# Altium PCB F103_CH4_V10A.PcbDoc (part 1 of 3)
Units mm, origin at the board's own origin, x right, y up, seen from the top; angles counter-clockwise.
Board outline 100.1 x 70.1 mm, 2 copper layers (TOP, BOTTOM), stack 1.6 mm thick; 116 components, 94 nets, 464 pads, 459 vias.
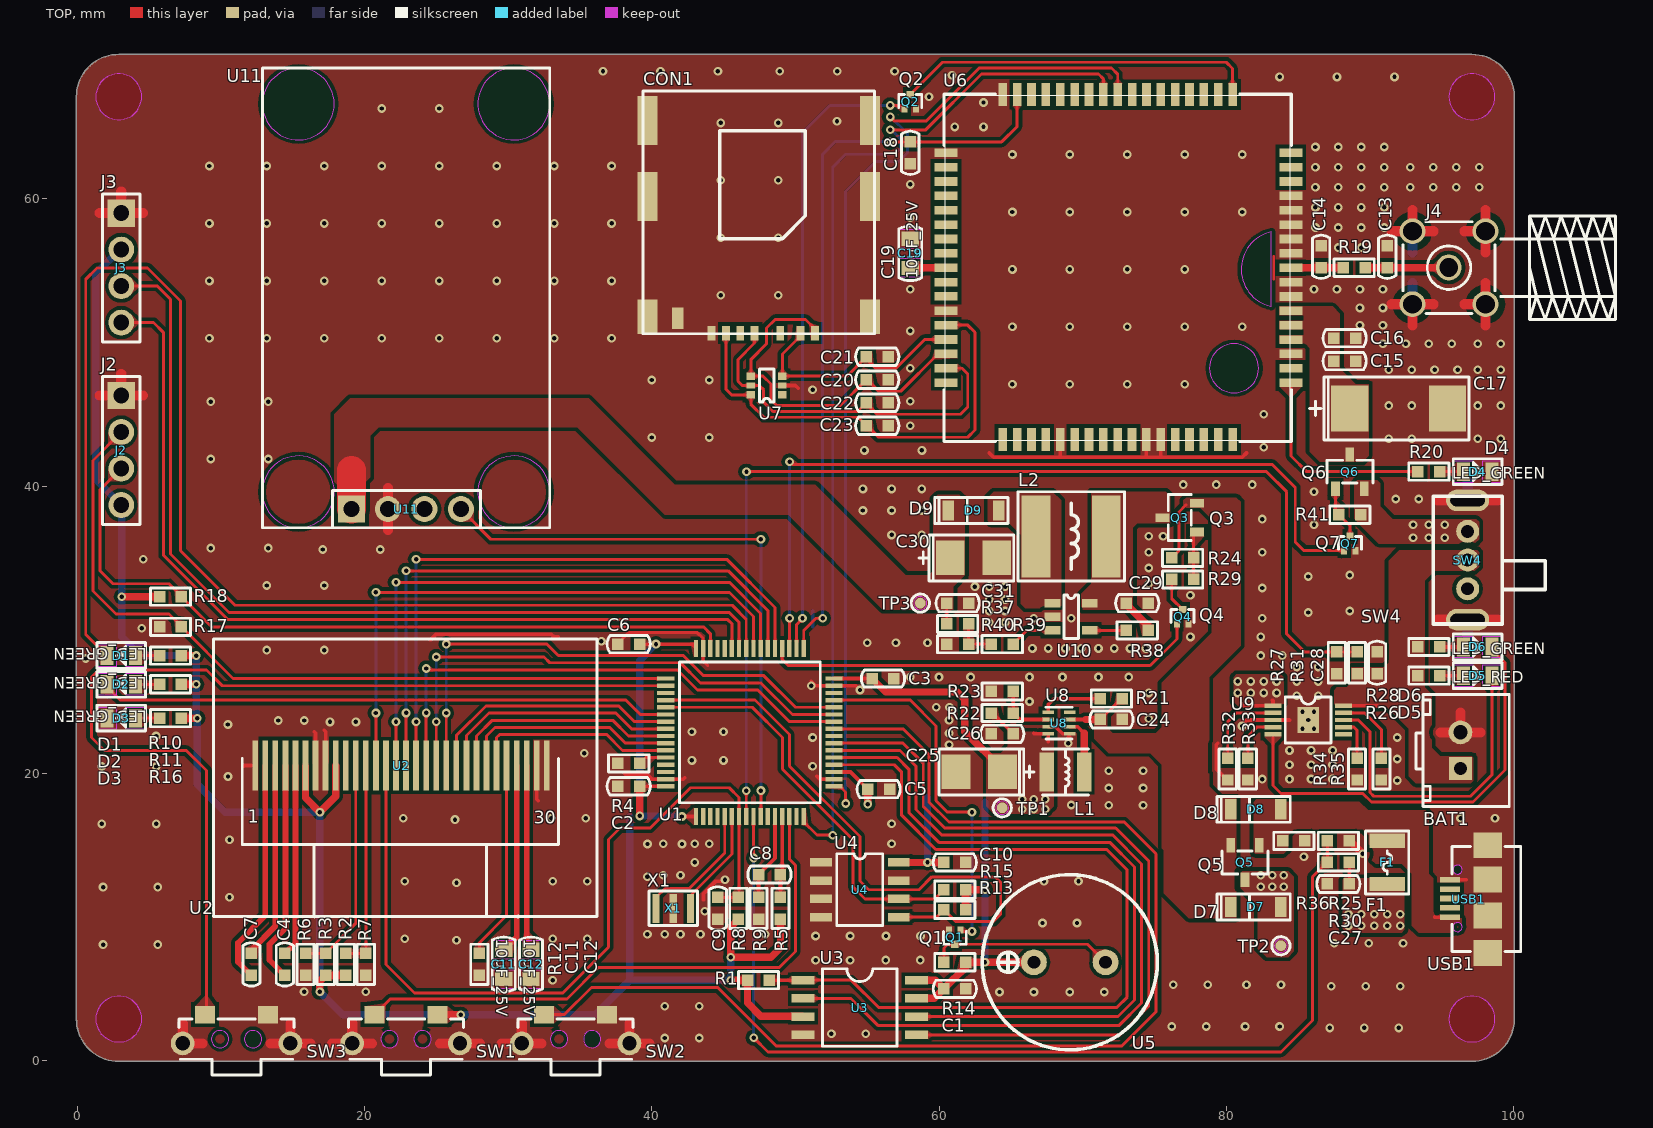
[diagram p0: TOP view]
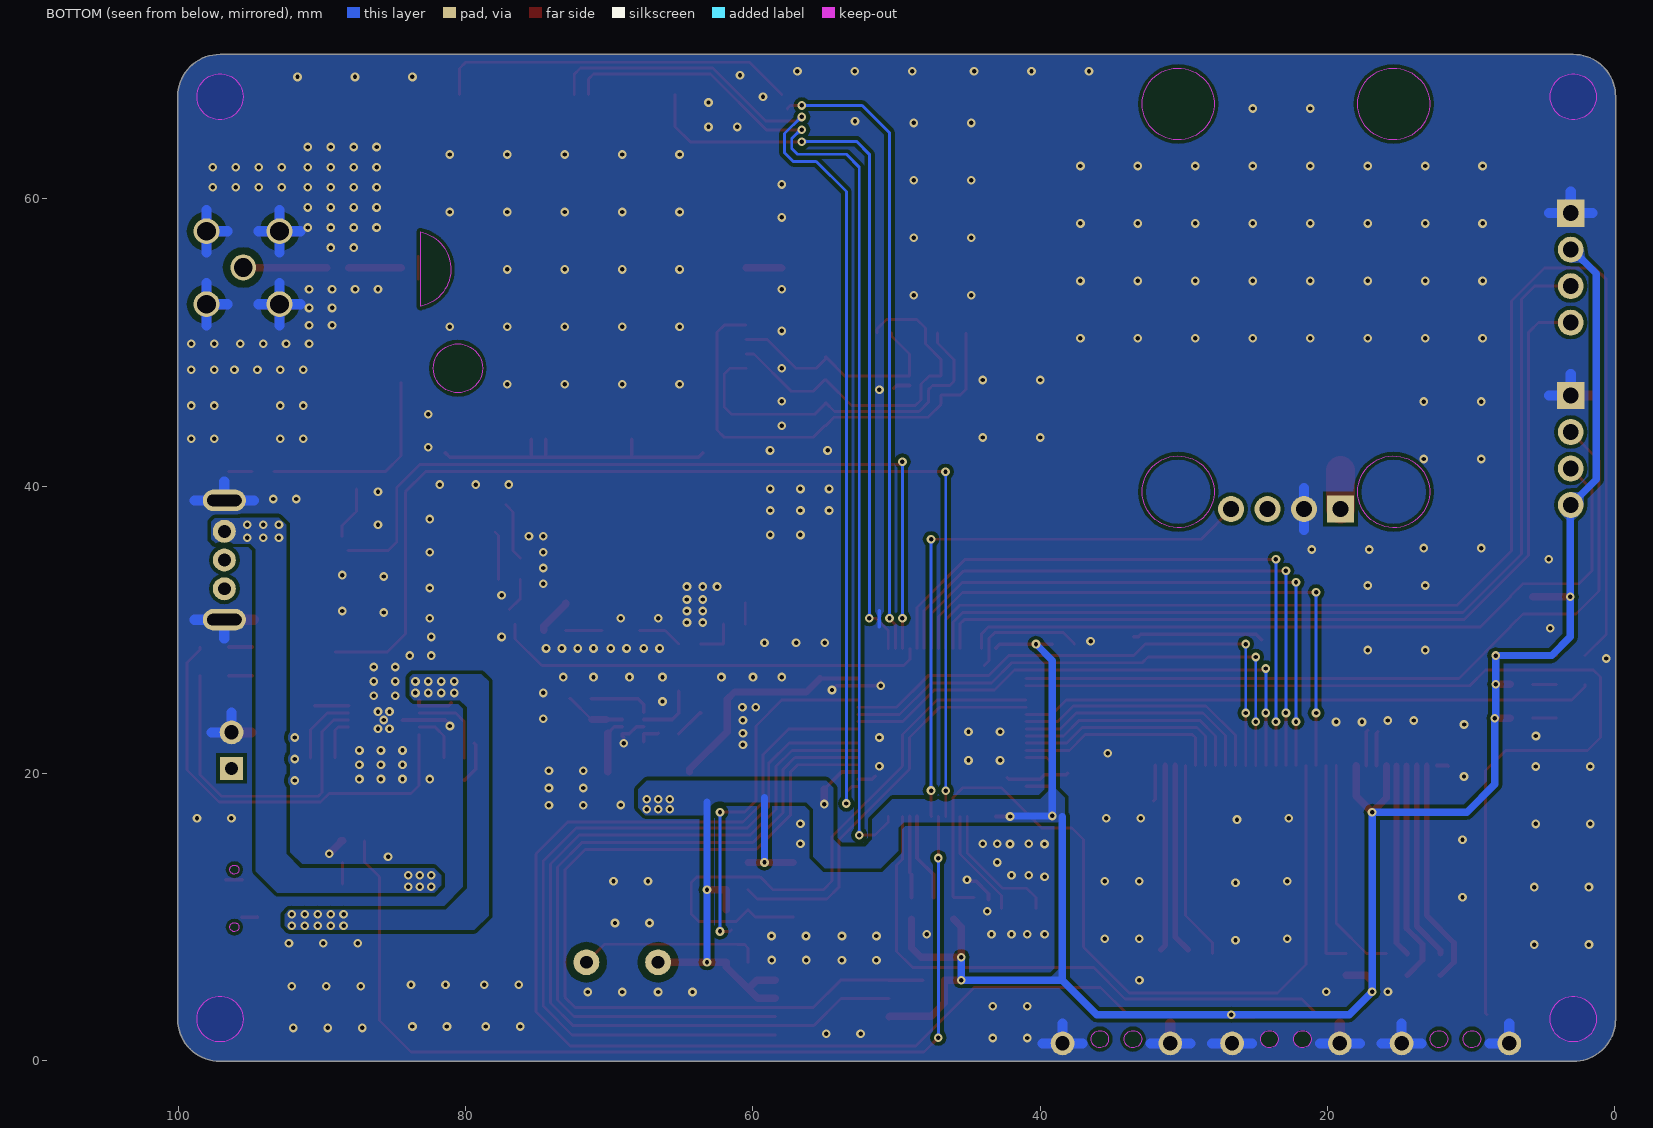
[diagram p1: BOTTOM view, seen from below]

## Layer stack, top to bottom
Top Solder: solder mask 0.0102, Solder Resist, Dk 3.5
TOP: signal copper 0.035
Dielectric 1: core 1.53, FR-4, Dk 4.5
BOTTOM: signal copper 0.035
Bottom Solder: solder mask 0.0102, Solder Resist, Dk 3.5

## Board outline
-0.05,2.9 ccw(c2.9,2.9) 2.9,-0.05 97.1,-0.05 ccw(c97.1,2.9) 100.05,2.899 100.05,2.9 100.05,67.1 100.05,67.101 ccw(c97.1,67.1) 97.1,70.05 2.9,70.05 ccw(c2.9,67.1) -0.05,67.1
cut-out: 4.5,67.1 ccw(c2.9,67.1)
cut-out: 4.5,2.9 ccw(c2.9,2.9)
cut-out: 98.7,2.9 ccw(c97.1,2.9)
cut-out: 98.7,67.1 ccw(c97.1,67.1)

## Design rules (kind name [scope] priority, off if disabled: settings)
Clearance [All] p1: gap=0.254 ignorepadtopadclearanceinfootprint=FALSE except(0: Arc-Hole Track-Hole SMDPad-Hole THPad-Hole Via-Hole Fill-Hole Poly-Hole Region-Hole Text-Hole)
PlaneConnect [All] p1: planeconnectstyle=Direct reliefexpansion=0.508 reliefentries=4 reliefconductorwidth=0.254 reliefairgap=0.254
PolygonConnect [All] p1: connectstyle=Direct reliefconductorwidth=0.254 reliefentries=4 polygonreliefangle="90 Angle" airgapwidth=0.254
RoutingVias [All] p1: holewidth=0.711 width=1.27 viastyle="Through Hole" minholewidth=0.711 minwidth=1.27 maxholewidth=0.711 maxwidth=1.27
SolderMaskExpansion [All] p1: expansion=0.102
Width [All] p1: maxlimit=0.254 minlimit=0.254 preferedwidth=0.254 impedanceprofiledriven=TRUE minimp=57.710000 maximp=185.620000 favimp=57.070000
29 further rules are at their usual default settings.

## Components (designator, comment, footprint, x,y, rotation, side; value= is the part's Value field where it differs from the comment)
BAT1 "BATTERY_XHB-2A_BATTERY" XHB-2A 96.3,21.6 r90 top
C1 "CAP NP_2_C0603_0.1UF_50V" C0603 61.1,5 r0 top
C2 "CAP NP_2_C0603_0.1UF_50V" C0603 38.4,19.1 r0 top
C3 "CAP NP_2_C0603_0.1UF_50V" C0603 56.1,26.6 r180 top
C4 "CAP NP_2_C0603_1UF_25V" C0603 14.462,6.7 r90 top
C5 "CAP NP_2_C0603_0.1UF_50V" C0603 55.8,18.9 r180 top
C6 "CAP NP_2_C0603_0.1UF_50V" C0603 38.4,29 r0 top
C7 "CAP NP_2_C0603_1UF_25V" C0603 12.138,6.7 r270 top
C8 "CAP NP_2_C0603_0.1UF_50V" C0603 48.2,12.956 r0 top
C9 "CAP NP_C0603_0.1UF_50V" C0603 44.6,10.6 r270 top
C10 "CAP NP_3_C0603_0.1UF_50V" C0603 61.1,13.8 r180 top
C11 "CAP NP_2_C0805_10UF_25V" C0805 29.7,6.7 r270 top
C12 "CAP NP_2_C0805_10UF_25V" C0805 31.6,6.7 r270 top
C13 "CAP NP_2_C0603_22PF_50V/NI" C0603 91.2,55.96 r270 top
C14 "CAP NP_2_C0603_22PF_50V/NI" C0603 86.6,55.96 r270 top
C15 "CAP NP_2_C0603_30PF_50V" C0603 88.238,48.7 r180 top
C16 "CAP NP_2_C0603_0.1UF_50V" C0603 88.238,50.3 r180 top
C17 "TMP_154254_C7343E_220UF_10V" C7343E 92,45.4 r180 top
C18 "CAP NP_2_C0603_0.1UF_50V" C0603 58,63.2 r90 top
C19 "CAP NP_0_C0805_10UF_25V" C0805 58,56.2 r90 top
C20 "CAP NP_2_C0603_30PF_50V" C0603 55.7,47.4 r0 top
C21 "CAP NP_2_C0603_30PF_50V" C0603 55.7,49 r0 top
C22 "CAP NP_2_C0603_30PF_50V" C0603 55.7,45.8 r0 top
C23 "CAP NP_2_C0603_0.1UF_50V" C0603 55.7,44.2 r180 top
C24 "CAP NP_2_C0603_10UF_10V" C0603 72,23.75 r0 top
C25 "TMP_154254_C3528B_47UF_10V" C3528B 62.8,20.1 r0 top
C26 "CAP NP_C0603_0.1UF_50V" C0603 64.4,22.75 r180 top
C27 "CAP NP_2_C0603_10UF_10V" C0603 87.8,12.3 r180 top
C28 "CAP NP_2_C0603_10UF_10V" C0603 90.5,27.7 r90 top
C29 "CAP NP_2_C0603_10UF_10V" C0603 73.8,31.85 r0 top
C30 "TMP_154254_C3528B_47UF_10V" C3528B 62.4,35 r180 top
C31 "CAP NP_C0603_0.1UF_50V" C0603 61.3,31.85 r0 top
CON1 "SIM_CARD_2_SIM_PUSH_5039600696" SIM_PUSH 39.4,50.6 r0 top
D1 "LED_4_LED0805_LED_GREEN" LED0805 3.074,28.2 r180 top
D2 "LED_4_LED0805_LED_GREEN" LED0805 3.074,26.2 r180 top
D3 "LED_4_LED0805_LED_GREEN" LED0805 3.074,23.845 r180 top
D4 "LED_4_LED0805_LED_GREEN" LED0805 97.5,41.004 r0 top
D5 "LED_4_LED0805_LED_RED" LED0805 97.5,26.8 r0 top
D6 "LED_4_LED0805_LED_GREEN" LED0805 97.5,28.8 r0 top
D7 "DIODE13_0_SOD123_LMBR130FT1G" SOD123 82.05,10.7 r0 top
D8 "DIODE13_0_SOD123_LMBR130FT1G" SOD123 82.05,17.5 r0 top
D9 "DIODE13_0_SOD123_LMBR130FT1G" SOD123 62.4,38.3 r0 top
F1 "FUSE_FUSE1210_SMD1210-200" FUSE1210 91.2,13.8 r270 top
J2 "CONN RCPT 4_HEADER4X1-2R54-M_HE" HEADER4X1-2R54-M 3.074,46.3 r270 top
J3 "CONN RCPT 4_HEADER4X1-2R54-M_HE" HEADER4X1-2R54-M 3.074,59 r270 top
J4 "SMA-50R_0_SMA-50R-DIP_SMA-50R" SMA-50R-DIP 95.5,55.2 r0 top
L1 "IND_BEAD_0805_600OHM_1_L3015_SW" L3015 68.8,20.1 r180 top
L2 "IND_BEAD_0805_600OHM_1_L6028_SW" L6028 69.2,36.5 r180 top
Q1 "DTC043ZMT2L_SOT723_DTC043ZMT2L" SOT723 61.1,8.6 r180 top
Q2 "DTC043ZMT2L_SOT723_DTC043ZMT2L" SOT723 58,66.751 r0 top
Q3 "MOS-P_0_SOT23-3_AO3401A" SOT23-3 76.762,37.8 r90 top
Q4 "DTC043ZMT2L_SOT723_DTC043ZMT2L" SOT723 76.962,30.9 r0 top
Q5 "MOS-P_SOT23-3_AO3401A" SOT23-3 81.3,13.8 r180 top
Q6 "MOS-P_0_SOT23-3_AO3401A" SOT23-3 88.6,41 r0 top
Q7 "DTC043ZMT2L_SOT723_DTC043ZMT2L" SOT723 88.6,36 r0 top
R1 "R_GENERIC_R0603_10K" R0603 47.432,5.605 r0 top
R2 "R_GENERIC_R0603_10K" R0603 18.7,6.7 r270 top
R3 "R_GENERIC_R0603_10K" R0603 17.3,6.7 r270 top
R4 "R_GENERIC_R0603_10K" R0603 38.4,20.7 r180 top
R5 "R_GENERIC_R0603_0R" R0603 48.962,10.6 r270 top
R6 "R_GENERIC_R0603_10K/NI" R0603 15.9,6.7 r90 top
R7 "R_GENERIC_R0603_10K/NI" R0603 20.1,6.7 r90 top
R8 "R_GENERIC_R0603_10K" R0603 46.032,10.6 r90 top
R9 "R_GENERIC_R0603_0R" R0603 47.438,10.6 r270 top
R10 "R_GENERIC_R0603_4.7K" R0603 6.5,28.2 r180 top
R11 "R_GENERIC_R0603_4.7K" R0603 6.5,26.2 r180 top
R12 "R_GENERIC_R0603_760K" R0603 28,6.7 r90 top
R13 "R_GENERIC_R0603_4.7K" R0603 61.1,10.5 r0 top
R14 "R_GENERIC_R0603_1K" R0603 61.1,6.85 r180 top
R15 "R_GENERIC_R0603_4.7K" R0603 61.1,11.9 r0 top
R16 "R_GENERIC_R0603_4.7K" R0603 6.5,23.845 r180 top
R17 "R_GENERIC_R0603_4.7K" R0603 6.5,30.2 r0 top
R18 "R_GENERIC_R0603_4.7K" R0603 6.5,32.3 r0 top
R19 "R_GENERIC_R0603_0R" R0603 88.9,55.198 r180 top
R20 "R_GENERIC_R0603_10K" R0603 94.1,41 r0 top
R21 "R_GENERIC_R0603_10K" R0603 72,25.2 r180 top
R22 "R_GENERIC_R0603_200K" R0603 64.4,24.2 r0 top
R23 "R_GENERIC_R0603_44.2K" R0603 64.4,25.7 r180 top
R24 "R_GENERIC_R0603_47K" R0603 76.962,35 r0 top
R25 "R_GENERIC_R0603_200K" R0603 87.8,15.3 r180 top
R26 "R_GENERIC_R0603_10K" R0603 94.1,26.8 r180 top
R27 "R_GENERIC_R0603_200K" R0603 87.7,27.7 r90 top
R28 "R_GENERIC_R0603_10K" R0603 94.1,28.8 r180 top
R29 "R_GENERIC_R0603_47K" R0603 76.962,33.5 r180 top
R30 "R_GENERIC_R0603_200K" R0603 87.8,13.8 r0 top
R31 "R_GENERIC_R0603_200K" R0603 89.1,27.7 r270 top
R32 "R_GENERIC_R0603_1.8K" R0603 80.1,20.3 r270 top
R33 "R_GENERIC_R0603_2K" R0603 81.5,20.3 r270 top
R34 "R_GENERIC_R0603_10K" R0603 89.1,20.3 r270 top
R35 "R_GENERIC_R0603_10K" R0603 90.8,20.3 r270 top
R36 "R_GENERIC_R0603_100K" R0603 84.7,15.3 r0 top
R37 "R_GENERIC_R0603_35.4K" R0603 61.3,30.4 r0 top
R38 "R_GENERIC_R0603_10K" R0603 73.8,29.95 r180 top
R39 "R_GENERIC_R0603_100K" R0603 64.4,29 r180 top
R40 "R_GENERIC_R0603_11.8K" R0603 61.3,29 r180 top
R41 "R_GENERIC_R0603_47K" R0603 88.6,38 r180 top
SW1 "SWITCH-SPST-4P_K2-1112SW-A4SW-0" K2-1112SW-A4SW-04 22.9,1.5 r180 top
SW2 "SWITCH-SPST-4P_K2-1112SW-A4SW-0" K2-1112SW-A4SW-04 34.7,1.5 r180 top
SW3 "SWITCH-SPST-4P_K2-1112SW-A4SW-0" K2-1112SW-A4SW-04 11.1,1.5 r180 top
SW4 "SWITCH_3P_SWITCH_3P_SWITCH_3P" SWITCH_3P 96.8,30.7 r90 top
TP1 "TESTPOINT_0_TP-0R75_TESTPOINT" TP-0R75 64.4,17.6 r0 top
TP2 "TESTPOINT_0_TP-0R75_TESTPOINT" TP-0R75 83.8,8 r0 top
TP3 "TESTPOINT_0_TP-0R75_TESTPOINT" TP-0R75 58.7,31.85 r0 top
U1 "STM32F103RXT6_LQFP64-10X10X0R5_" LQFP64-10X10X0R5 46.832,22.85 r0 top
U2 "OLED_0_OLED_0R96_OLED_0R96" OLED_0R96 22.9,19.745 r0 top
U3 "W25QXX_SOIC8_208_W25Q64JVSSIQ" SOIC8_208 54.485,3.7 r270 top
U4 "AT24C512_SOIC8_AT24C512C-SSHM-T" SOIC8 54.485,11.9 r270 top
U5 "PS1240P02BT_PS1240P02BT_PS1240P" PS1240P02BT 69.1,6.85 r0 top
U6 "SIM800A_SIM800A_SIM800A" SIM800A 72.438,55.2 r270 top
U7 "SMF05CT1G_SOT363_SMF05C" SOT363 48,47 r90 top
U8 "MP2162GQH-Z_QFN8-2X1R5X0R5_MP21" QFN8-2X1R5X0R5 68.35,23.5 r0 top
U9 "BQ24090_MSOP10-1R80X1R50_BQ2409" MSOP10-1R80X1R50 85.7,23.713 r270 top
U10 "MP1540DJ-LF-Z_SOT23-5_MP1540DJ-" SOT23-5 69.2,30.9 r270 top
U11 "MQ-4-MODULE_MQ-4-MODULE_MQ-4-MO" MQ-4-MODULE 19.1,38.4 r0 top
USB1 "USB-MICRO_USB-MICRO_USB-MICRO" USB-MICRO 95.5,11.3 r90 top
X1 "XTAL_5032_0_X-3P-3R2X1R3-SMD_CS" X-3P-3R2X1R3-SMD 41.5,10.6 r0 top

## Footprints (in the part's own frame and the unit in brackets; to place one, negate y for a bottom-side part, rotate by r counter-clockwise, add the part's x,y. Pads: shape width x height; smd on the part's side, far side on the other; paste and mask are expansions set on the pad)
C0603 [mm] "C0603"
  rect 0.8x0.8 smd: 1(-0.762,0) 2(0.762,0)
  silkscreen extent -1.51,-0.6 1.51,0.6, body extent -0.89,-0.38 0.89,0.38, height 3.81
C0805 [mm] "C0805"
  rect 1x1.2 smd: 1(-1.016,0) 2(1.016,0)
  TOP keep-out region: 0.356,0.762 1.676,0.762 1.676,-0.762 0.356,-0.762 0.356,0.762
  TOP keep-out region: -1.676,0.762 -0.356,0.762 -0.356,-0.762 -1.676,-0.762 -1.676,0.762
  silkscreen extent -1.9,-0.8 1.9,0.8, body extent -1,-0.6 1,0.6, height 3.81
C3528B [mm] "C3528B"
  rect 2x2.4 smd: 1(1.615,0) 2(-1.614,0)
  silkscreen extent -2.8,-1.6 3.8,1.6, body extent -1.8,-1.4 1.8,1.4, height 3.81
C7343E [mm] "C7343E"
  rect 2.6x3.2 smd: 1(3.4,0) 2(-3.4,0)
  silkscreen extent -4.9,-2.2 6.2,2.2, body extent -3.7,-2.2 3.7,2.2, height 3.81
FUSE1210 [mm] "FUSE1210"
  rect 1x2.5 smd: 1(-1.5,0) 2(1.5,0)
  silkscreen extent -2.2,-1.5 2.2,1.5, body extent -1.7,-1.4 1.7,1.4, height 3.81
HEADER4X1-2R54-M [mm] "HEADER4X1-2R54-M"
  rect 1.9x1.9 / inner round 1.524 / far side rect 1.9x1.9 hole 1.1: 1(0,0)
  round 1.8 / inner round 1.524 / far side round 1.8 hole 1.1: 2(2.54,0) 3(5.08,0) 4(7.62,0)
  silkscreen extent -1.33,-1.8 8.97,1.3, body extent -1.23,-1.2 8.87,1.2, height 3.81
K2-1112SW-A4SW-04 [mm] "K2-1112SW-A4SW-04"
  round 1.65 / inner round 1.524 / far side round 1.65 hole 1: 1(-3.75,0.3) 4(3.75,0.3)
  rect 1.4x1.2 smd: 2(-2.2,-1.7) 3(2.2,-1.7)
  Multi-Layer keep-out circle w0.025: c1.15,0 r0.6
  Multi-Layer keep-out circle w0.025: c-1.15,0 r0.6
  silkscreen extent -4,-1.4 4,2.5, body extent -3.85,-1.2 3.85,2.3, height 3.81
L3015 [mm] "L3015"
  rect 1x2.7 smd: 1(-1.3,0) 2(1.3,0)
  silkscreen extent -1.6,-1.6 1.6,1.6, body extent -1.5,-1.5 1.5,1.5, height 3.81
L6028 [mm] "L6028"
  rect 2x5.7 smd: 1(-2.45,0) 2(2.45,0)
  silkscreen extent -3.7,-3.1 3.7,3.1, body extent -3,-3 3,3, height 3.81
LED0805 [mm] "LED0805"
  rect 0.9x1.3 smd: 1(-1,0) 2(1,0)
  TOP keep-out region: 0.356,0.762 1.676,0.762 1.676,-0.762 0.356,-0.762 0.356,0.762
  TOP keep-out region: -1.676,0.762 -0.356,0.762 -0.356,-0.762 -1.676,-0.762 -1.676,0.762
  silkscreen extent -1.7,-0.9 1.7,0.9, body extent -1,-0.6 1,0.6, height 3.81
LQFP64-10X10X0R5 [mm] "LQFP64-10X10X0R5"
  rect 0.3x1.2 smd: 1(-3.75,-5.85) 2(-3.25,-5.85) 3(-2.75,-5.85) 4(-2.25,-5.85) 5(-1.75,-5.85) 6(-1.25,-5.85) 7(-0.75,-5.85) 8(-0.25,-5.85) 9(0.25,-5.85) 10(0.75,-5.85) 11(1.25,-5.85) 12(1.75,-5.85) 13(2.25,-5.85) 14(2.75,-5.85) 15(3.25,-5.85) 16(3.75,-5.85) 33(3.75,5.85) 34(3.25,5.85) 35(2.75,5.85) 36(2.25,5.85) 37(1.75,5.85) 38(1.25,5.85) 39(0.75,5.85) 40(0.25,5.85) 41(-0.25,5.85) 42(-0.75,5.85) 43(-1.25,5.85) 44(-1.75,5.85) 45(-2.25,5.85) 46(-2.75,5.85) 47(-3.25,5.85) 48(-3.75,5.85)
  rect 1.2x0.3 smd: 17(5.85,-3.75) 18(5.85,-3.25) 19(5.85,-2.75) 20(5.85,-2.25) 21(5.85,-1.75) 22(5.85,-1.25) 23(5.85,-0.75) 24(5.85,-0.25) 25(5.85,0.25) 26(5.85,0.75) 27(5.85,1.25) 28(5.85,1.75) 29(5.85,2.25) 30(5.85,2.75) 31(5.85,3.25) 32(5.85,3.75) 49(-5.85,3.75) 50(-5.85,3.25) 51(-5.85,2.75) 52(-5.85,2.25) 53(-5.85,1.75) 54(-5.85,1.25) 55(-5.85,0.75) 56(-5.85,0.25) 57(-5.85,-0.25) 58(-5.85,-0.75) 59(-5.85,-1.25) 60(-5.85,-1.75) 61(-5.85,-2.25) 62(-5.85,-2.75) 63(-5.85,-3.25) 64(-5.85,-3.75)
  silkscreen extent -4.9,-7.21 4.9,4.9, body extent -5,-5 5,5, height 3.81
MQ-4-MODULE [mm] "MQ-4-MODULE"
  rect 1.9x1.9 / inner round 1.524 / far side rect 1.9x1.9 hole 1.1: 1(0,0)
  round 1.8 / inner round 1.524 / far side round 1.8 hole 1.1: 2(2.54,0) 3(5.08,0) 4(7.62,0)
  Multi-Layer keep-out circle w0.025: c-3.7,28.2 r2.5
  Multi-Layer keep-out circle w0.025: c11.3,28.2 r2.5
  Multi-Layer keep-out circle w0.025: c11.3,1.2 r2.5
  Multi-Layer keep-out circle w0.025: c-3.7,1.2 r2.5
  silkscreen extent -6.2,-1.8 13.8,30.7, body extent -6.2,-1.3 13.8,30.7, height 3.81
MSOP10-1R80X1R50 [mm] "MSOP10-1R80X1R50"
  rect 0.3x1.2 smd: 1(-1,-2.45) 2(-0.5,-2.45) 3(0,-2.45) 4(0.5,-2.45) 5(1,-2.45) 6(1,2.45) 7(0.5,2.45) 8(0,2.45) 9(-0.5,2.45) 10(-1,2.45)
  rect 1.8x1.5 smd: 11(0,0)
  silkscreen extent -1.6,-3.81 1.6,1.6, body extent -1.5,-1.5 1.5,1.5, height 3.81
OLED_0R96 [mm] "OLED_0R96"
  rect 0.4x3.5 smd: 1(-10.5,0.8) 2(-9.8,0.8) 3(-9.1,0.8) 4(-8.4,0.8) 5(-7.7,0.8) 6(-7,0.8) 7(-6.3,0.8) 8(-5.6,0.8) 9(-4.9,0.8) 10(-4.2,0.8) 11(-3.5,0.8) 12(-2.8,0.8) 13(-2.1,0.8) 14(-1.4,0.8) 15(-0.7,0.8) 16(0,0.8) 17(0.7,0.8) 18(1.4,0.8) 19(2.1,0.8) 20(2.8,0.8) 21(3.5,0.8) 22(4.2,0.8) 23(4.9,0.8) 24(5.6,0.8) 25(6.3,0.8) 26(7,0.8) 27(7.7,0.8) 28(8.4,0.8) 29(9.1,0.8) 30(9.8,0.8)
  silkscreen extent -13.4,-9.74 13.3,9.6, body extent -13.4,-9.7 13.3,9.6, height 3.81
PS1240P02BT [mm] "PS1240P02BT"
  round 1.8 / inner round 1.524 / far side round 1.8 hole 0.9: 1(-2.5,0) 2(2.5,0)
  silkscreen extent -6.1,-6.1 6.1,6.1, body extent -6.11,-6.11 6.11,6.11, height 3.81
QFN8-2X1R5X0R5 [mm] "QFN8-2X1R5X0R5"
  rect 0.8x0.25 smd: 1(-0.75,0.75) 2(-0.75,0.25) 3(-0.75,-0.25) 4(-0.75,-0.75) 5(0.75,-0.75) 6(0.75,-0.25) 7(0.75,0.25) 8(0.75,0.75)
  silkscreen extent -1.7,-1.1 0.9,1.1, body extent -0.8,-1.05 0.8,1.05, height 3.81
R0603 [mm] "R0603"
  rect 0.8x0.8 smd: 1(-0.762,0) 2(0.762,0)
  silkscreen extent -1.4,-0.6 1.4,0.6, body extent -0.89,-0.38 0.89,0.38, height 3.81
SIM800A [mm] "SIM800A"
  rect 1.6x0.6 smd: 1(-12.051,8.002) 2(-12.051,7.002) 3(-12.051,6.002) 4(-12.051,5.002) 5(-12.051,4.002) 6(-12.051,3.002) 7(-12.051,2.002) 8(-12.051,1.002) 9(-12.051,0.002) 10(-12.051,-0.998) 11(-12.051,-1.998) 12(-12.051,-2.998) 13(-12.051,-3.998) 14(-12.051,-4.998) 15(-12.051,-5.998) 16(-12.051,-6.998) 17(-12.051,-7.998) 35(11.949,-8) 36(11.949,-7) 37(11.949,-6) 38(11.949,-5) 39(11.949,-4) 40(11.949,-3) 41(11.949,-2) 42(11.949,-1) 43(11.949,0) 44(11.949,1) 45(11.949,2) 46(11.949,3) 47(11.949,4) 48(11.949,5) 49(11.949,6) 50(11.949,7) 51(11.949,8)
  rect 0.6x1.6 smd: 18(-8,-11.949) 19(-7,-11.949) 20(-6,-11.949) 21(-5,-11.949) 22(-4,-11.949) 23(-3,-11.949) 24(-2,-11.949) 25(-1,-11.949) 26(0,-11.949) 27(1,-11.949) 28(2,-11.949) 29(3,-11.949) 30(4,-11.949) 31(5,-11.949) 32(6,-11.949) 33(7,-11.949) 34(8,-11.949) 52(8.002,12.051) 53(7.002,12.051) 54(6.002,12.051) 55(5.002,12.051) 56(4.002,12.051) 57(3.002,12.051) 58(2.002,12.051) 59(1.002,12.051) 60(0.002,12.051) 61(-0.998,12.051) 62(-1.998,12.051) 63(-2.998,12.051) 64(-3.998,12.051) 65(-4.998,12.051) 66(-5.998,12.051) 67(-6.998,12.051) 68(-7.998,12.051)
  Multi-Layer keep-out circle w0.025: c7,8.1 r1.709
  Multi-Layer keep-out region: 0.8,10.7 -2.5,10.7 -2.5,10.7 -2.442,10.476 -2.364,10.257 -2.267,10.046 -2.153,9.844 -2.021,9.653 -1.873,9.475 -1.71,9.309 -1.534,9.159 -1.345,9.025 -1.144,8.907 -0.935,8.808 -0.717,8.727 -0.494,8.665 -0.266,8.623 -0.035,8.602 0.197,8.6 0.428,8.618 0.657,8.657 0.882,8.716 1.1,8.793 1.311,8.89 1.513,9.004 1.704,9.136 1.883,9.284 2.048,9.447 2.198,9.624 2.332,9.813 2.45,10.013 2.549,10.222 2.63,10.44 2.692,10.663 2.7,10.7 0.8,10.7
  silkscreen extent -13.73,-12.1 12.1,12.1, body extent -12,-12 12,12, height 3.81
SIM_PUSH [mm] "SIM_PUSH"
  rect 0.55x1 smd: 1(5.765,0.05) 2(7.765,0.05) 3(11.955,0.05) 4(9.55,0.05) 5(4.765,0.05) 6(6.765,0.05) 7(10.955,0.05)
  rect 1.4x2.4 smd: 8(0.3,1.2) 13(15.8,1.2)
  rect 1.4x3.4 smd: 9(0.3,9.55) 10(0.3,14.85) 11(15.8,14.85) 12(15.8,9.55)
  rect 0.8x1.5 smd: 14(2.4,1.07)
  silkscreen extent 0,0 16.1,16.9
SMA-50R-DIP [mm] "SMA-50R-DIP"
  round 1.8 / inner round 1.524 / far side round 1.8 hole 1.3: 1(-0.016,0.016) 2(-2.54,2.54) 3(-2.54,-2.54) 4(2.54,-2.54) 5(2.54,2.54)
  silkscreen extent -3.2,-3.6 11.6,3.6, body extent -3.2,-3.2 3.2,3.2, height 3.81
SOD123 [mm] "SOD123"
  rect 0.8x1.4 smd: 1(1.75,0) 2(-1.75,0)
  silkscreen extent -2.7,-0.9 2.4,0.9, body extent -1.7,-0.64 1.73,0.64, height 3.81
SOIC8 [mm] "SOIC8"
  rect 0.6x1.5 smd: 1(-1.9,-2.7) 2(-0.63,-2.7) 3(0.64,-2.7) 4(1.91,-2.7) 5(1.91,2.7) 6(0.64,2.7) 7(-0.63,2.7) 8(-1.9,2.7)
  silkscreen extent -2.5,-4.21 2.5,1.6, body extent -2.5,-2 2.5,2, height 3.81
SOIC8_208 [mm] "SOIC8_208"
  rect 0.6x1.6 smd: 1(-1.905,-3.95) 2(-0.635,-3.95) 3(0.635,-3.95) 4(1.905,-3.95) 5(1.905,3.95) 6(0.635,3.95) 7(-0.635,3.95) 8(-1.905,3.95)
  silkscreen extent -2.7,-5.51 2.7,2.6, body extent -2.7,-2.6 2.7,2.6, height 3.81
SOT23-3 [mm] "SOT23-3"
  rect 0.6x1 smd: 1(-1,-1.2) 2(1,-1.2) 3(0,1.2)
  silkscreen extent -1.6,-0.8 1.6,0.8, body extent -1.5,-0.7 1.5,0.7, height 3.81
SOT23-5 [mm] "SOT23-5"
  rect 0.6x1.1 smd: 1(-0.95,-1.3) 2(0,-1.3) 3(0.95,-1.3) 4(0.95,1.3) 5(-0.95,1.3)
  silkscreen extent -1.52,-2.54 1.52,0.51, body extent -1.5,-0.8 1.5,0.8, height 3.81
SOT363 [mm] "SOT363"
  rect 0.5x0.6 smd: 1(-0.65,-1.1) 3(0.65,-1.1) 4(0.65,1.1) 6(-0.65,1.1)
  rect 0.4x0.6 smd: 2(0,-1.1) 5(0,1.1)
  silkscreen extent -1.14,-2.04 1.14,0.51, body extent -1.1,-0.6 1.1,0.6, height 3.81
SOT723 [mm] "SOT723"
  rect 0.4x0.5 smd: 1(-0.4,-0.5) 2(0.4,-0.5)
  rect 0.5x0.5 smd: 3(0,0.5)
  silkscreen extent -0.8,-0.4 0.8,0.5, body extent -0.65,-0.45 0.65,0.45, height 3.81
SWITCH_3P [mm] "SWITCH_3P"
  oval 1.5x3 / inner round 1.524 / far side oval 1.5x3 hole 0.8 slot 2.4 at 90 deg: 1(0,0) 5(8.3,0)
  round 1.6 / inner round 1.524 / far side round 1.6 hole 0.9: 2(2.15,0) 3(4.15,0) 4(6.15,0)
  silkscreen extent -0.3,-5.4 8.6,2.4, body extent -0.2,-5.4 8.5,2.3, height 3.81
TP-0R75 [mm] "TP-0R75"
  round 0.75 smd: 1(0,0)
  TOP keep-out circle w0.025: c0,0 r0.457
  silkscreen extent -0.63,-0.63 0.64,0.63, body extent -0.47,-0.47 0.47,0.47, height 3.81
USB-MICRO [mm] "USB-MICRO"
  rect 0.4x1.4 smd: 1(-1.31,-0.07) 2(-0.66,-0.07) 3(-0.01,-0.07) 4(0.64,-0.07) 5(1.29,-0.07)
  rect 1.8x2 smd: 6(-3.8,-2.7) 7(-1.2,-2.7) 8(1.3,-2.7) 9(3.7,-2.7)
  Multi-Layer keep-out circle w0.025: c2,-0.6 r0.316
  Multi-Layer keep-out circle w0.025: c-2,-0.6 r0.316
  silkscreen extent -3.7,-5 3.6,-0.2, body extent -3.6,-4.9 3.5,-0.3, height 3.81
X-3P-3R2X1R3-SMD [mm] "X-3P-3R2X1R3-SMD"
  rect 0.5x2 smd: 1(-1.2,0) 2(0,0) 3(1.2,0)
  silkscreen extent -1.7,-1.2 1.7,1.2, body extent -1.6,-0.65 1.6,0.65, height 3.81
XHB-2A [mm] "XHB-2A"
  rect 1.6x1.6 / inner round 1.524 / far side rect 1.6x1.6 hole 0.9: 1(-1.25,0)
  round 1.65 / inner round 1.524 / far side round 1.65 hole 1: 2(1.25,0)
  silkscreen extent -3.9,-3.4 3.9,3.1, body extent -3.8,-3.3 3.8,2.5, height 3.81

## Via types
v1: diameter 0.61, hole 0.305, TOP to BOTTOM, tented both sides, 459 vias

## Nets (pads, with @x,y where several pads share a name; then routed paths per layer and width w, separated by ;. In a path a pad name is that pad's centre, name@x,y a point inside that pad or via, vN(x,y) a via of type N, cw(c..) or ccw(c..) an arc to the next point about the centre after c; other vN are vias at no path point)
ADC_BAT: R27.2 R31.1 U1.8 | length 77.5
  TOP w0.203: U1.8@46.582,17 v1(46.582,18.782) ; v1(46.6,41) 82.8,41 84.2,39.6 84.2,29.7 85.438,28.462 R27.2@87.7,28.462 R31.1@89.1,28.462
  BOTTOM w0.203: v1(46.582,18.782) 46.582,40.982 v1(46.6,41)
ADC_USB: R25.2 R30.1 U1.9 | length 68.6
  TOP w0.203: U1.9@47.082,17 47.1,16.982 v1(47.1,14.1) ; v1(47.1,1.6) 48.1,0.6 83.8,0.6 86,2.8 86,12.8 87,13.8 R30.1@87.038,13.8 R25.2@87.038,15.3
  BOTTOM w0.203: v1(47.1,1.6) v1(47.1,14.1)
BOOT0: R4.1 U1.60 | length 2
  TOP w0.203: R4.1@39.162,20.7 39.562,21.1 U1.60@40.982,21.1
BS1: R3.1 R6.2 U2.11 | length 15.4
  TOP w0.203: R6.2@15.9,7.462 R3.1@17.3,7.462 19.4,9.562 U2.11@19.4,20.545
BS2: R2.1 R7.2 U2.12 | length 14.5
  TOP w0.203: R2.1@18.7,7.462 R7.2@20.1,7.462 U2.12@20.1,20.545
CTL_BEEP: Q1.1 U1.29 | length 25
  TOP w0.203: U1.29@52.682,25.1 58,25.1 59.8,23.3 59.8,18.1 60.6,17.3 v1(62.3,17.3) ; Q1.1@61.5,9.1 61.6,9 v1(62.3,9)
  BOTTOM w0.203: v1(62.3,9) v1(62.3,17.3)
CTL_GPRS: Q7.1 U1.35 | length 56.4
  TOP w0.203: U1.35@49.582,28.7 49.6,28.718 v1(49.6,30.8) ; v1(49.6,41.7) 49.8,41.5 83.2,41.5 84.8,39.9 84.8,36.1 85.4,35.5 Q7.1@88.2,35.5
  BOTTOM w0.203: v1(49.6,30.8) v1(49.6,41.7)
CTL_SENSOR: Q4.1 U1.36 | length 30.2
  TOP w0.203: U1.36@49.082,28.7 49.082,27.918 49.5,27.5 74.7,27.5 76.562,29.362 Q4.1@76.562,30.4
F_CS: R1.2 U1.20 U3.1 | length 60.1
  TOP w0.203: U3.1@50.535,5.605 53.895,5.605 55.8,3.7 72.378,3.7 73.1,4.422 73.1,13.278 71.678,14.7 59.778,14.7 57.4,17.078 57.4,20.078 56.878,20.6 U1.20@52.682,20.6
  TOP w0.254: R1.2@48.194,5.605 U3.1@50.535,5.605
GND: BAT1.2 C1.2 C2.1 C3.1 C5.1 C6.1 C9.2 C10.1 C11.2 C12.2 C13.1 C14.1 C15.1 C16.1 C17.2 C18.1 C19.2 C20.2 C21.2 C22.2 C23.1 C24.2 C25.2 C26.2 C27.2 C28.2 C29.2 C30.2 C31.2 CON1.5 CON1.8 CON1.9 CON1.10 CON1.11 CON1.12 CON1.13 CON1.14 D3.2 D4.2 J2.1 J3.1 J4.2 J4.3 J4.4 J4.5 Q1.2 Q2.2 Q4.2 Q7.2 R4.2 R6.1 R7.1 R9.2 R12.1 R17.1 R23.2 R25.1 R27.1 R32.2 R33.2 R34.2 R35.2 R36.2 R40.2 SW1.1 SW1.4 SW2.1 SW2.2 SW2.4 SW3.1 SW3.2 SW3.4 SW4.1 SW4.5 U1.18 U1.31 U1.47 U1.63 U2.1 U2.7 U2.8 U2.29 U2.30 U3.4 U4.1 U4.2 U4.3 U4.4 U4.7 U6.17 U6.18 U6.29 U6.39 U6.45 U6.46 U6.54 U6.58 U6.59 U6.61 U6.62 U6.63 U6.64 U6.65 U7.2 U8.3 U8.5 U9.3 U9.11 U10.2 U11.2 USB1.5 USB1.6 USB1.7 USB1.8 USB1.9 X1.2 | length 199.9
  TOP w0.203: C6.1@37.638,29 37.638,29.038 38.394,29.794 43.169,29.794 43.582,29.381 U1.47@43.582,28.7 43.582,27.818 43.9,27.5 ; 83.3,54.4 83.3,56
  TOP w0.254: 11.6,20.5 11.645,20.545 U2.1@12.4,20.545 ; 16.5,22.9 16.6,22.8 U2.7@16.6,20.545 ; 17.2,23 17.3,22.9 U2.8@17.3,20.545 ; 24.6,29.3 24.986,29.686 33.014,29.686 33.2,29.5 33.5,29.5 ; U2.29@32,20.545 32,18.2 32.1,18.1 ; 38.1,20 38.2,19.9 39.7,19.9 40,19.6 U1.63@40.982,19.6 42.2,19.6 42.3,19.7 ; 43.6,11.2 43.6,11.629 44.471,12.5 45,12.5 v1(45.1,12.6) ; U7.2@49.1,47 50,47 50.2,46.8 ; v1@51.1,26.4 51.4,26.1 U1.31@52.682,26.1 54.2,26.1 v1(54.5,25.8) ; 51.5,19.8 51.7,19.6 U1.18@52.682,19.6 ; 63.5,42.3 63.8,42 68.4,42 ; U8.3@67.6,23.25 68.108,23.25 68.608,22.75 U8.5@69.1,22.75 69.1,22.6 69,22.5 ; U6.39@68.438,43.251 68.438,42.038 68.4,42 ; U6.45@74.438,43.251 74.438,42.038 74.4,42 ; U6.46@75.438,43.251 75.438,42.038 75.4,42 ; 79.4,22.1 79.3,22 79.3,20.3 80.062,19.538 R32.2@80.1,19.538 ; v1@81.2,23.5 81.413,23.713 U9.3@83.25,23.713 84.387,23.713 84.4,23.7 ; 81.4,42.3 81.1,42 75.4,42 ; USB1.5@95.57,12.59 96.69,12.59 96.7,12.6 ; 68.4,42 74.4,42 ; 74.4,42 75.4,42
  TOP w0.508: R25.1@88.562,15.3 88.7,15.3 88.7,15.2 v1(89.5,14.4)
  TOP w0.711: 1.565,46.3 J2.1@3.074,46.3 ; 1.565,59 J3.1@3.074,59 ; 3.074,47.809 J2.1@3.074,46.3 ; 3.074,60.509 J3.1@3.074,59 ; 4.583,46.3 J2.1@3.074,46.3 ; 4.583,59 J3.1@3.074,59 ; 7.35,2.584 SW3.4@7.35,1.2 8.734,1.2 ; 13.466,1.2 SW3.1@14.85,1.2 ; 14.85,2.584 SW3.1@14.85,1.2 ; 16.234,1.2 SW3.1@14.85,1.2 ; 17.766,1.2 SW1.4@19.15,1.2 ; 19.15,2.584 SW1.4@19.15,1.2 ; 20.534,1.2 SW1.4@19.15,1.2 ; 21.64,36.941 U11.2@21.64,38.4 21.64,39.859 ; 25.266,1.2 SW1.1@26.65,1.2 28.034,1.2 ; 29.566,1.2 SW2.4@30.95,1.2 ; 30.95,2.584 SW2.4@30.95,1.2 ; 32.334,1.2 SW2.4@30.95,1.2 ; 37.066,1.2 SW2.1@38.45,1.2 ; 38.45,2.584 SW2.1@38.45,1.2 ; 39.834,1.2 SW2.1@38.45,1.2 ; 91.501,52.66 J4.3@92.96,52.66 ; 91.501,57.74 J4.2@92.96,57.74 ; 92.96,51.201 J4.3@92.96,52.66 ; 92.96,59.199 J4.2@92.96,57.74 ; 94.419,52.66 J4.3@92.96,52.66 ; 94.419,57.74 J4.2@92.96,57.74 ; 94.741,30.7 SW4.1@96.8,30.7 98.859,30.7 ; 94.741,39 SW4.5@96.8,39 98.859,39 ; 94.916,22.85 BAT1.2@96.3,22.85 ; 96.3,24.234 BAT1.2@96.3,22.85 ; 96.581,52.66 J4.4@98.04,52.66 ; 96.581,57.74 J4.5@98.04,57.74 ; 97.684,22.85 BAT1.2@96.3,22.85 ; 98.04,51.201 J4.4@98.04,52.66 ; 98.04,54.119 J4.4@98.04,52.66 ; 98.04,56.281 J4.5@98.04,57.74 ; 98.04,59.199 J4.5@98.04,57.74
  BOTTOM w0.254: 51.2,30.2 51.2,31.3
  BOTTOM w0.711: 1.565,59 J3.1@3.074,59 ; 3.074,47.809 J2.1@3.074,46.3 4.583,46.3 ; 3.074,60.509 J3.1@3.074,59 ; 4.583,59 J3.1@3.074,59 ; 7.35,2.584 SW3.4@7.35,1.2 8.734,1.2 ; 13.466,1.2 SW3.1@14.85,1.2 ; 14.85,2.584 SW3.1@14.85,1.2 ; 16.234,1.2 SW3.1@14.85,1.2 ; 17.766,1.2 SW1.4@19.15,1.2 20.534,1.2 ; 21.64,36.941 U11.2@21.64,38.4 21.64,39.859 ; 25.266,1.2 SW1.1@26.65,1.2 28.034,1.2 ; 29.566,1.2 SW2.4@30.95,1.2 32.334,1.2 ; 37.066,1.2 SW2.1@38.45,1.2 ; 38.45,2.584 SW2.1@38.45,1.2 ; 39.834,1.2 SW2.1@38.45,1.2 ; 91.501,52.66 J4.3@92.96,52.66 ; 91.501,57.74 J4.2@92.96,57.74 ; 92.96,51.201 J4.3@92.96,52.66 ; 92.96,54.119 J4.3@92.96,52.66 ; 92.96,56.281 J4.2@92.96,57.74 ; 92.96,59.199 J4.2@92.96,57.74 ; 94.419,52.66 J4.3@92.96,52.66 ; 94.419,57.74 J4.2@92.96,57.74 ; 94.741,39 SW4.5@96.8,39 ; 96.3,24.234 BAT1.2@96.3,22.85 97.684,22.85 ; 96.581,52.66 J4.4@98.04,52.66 ; 96.581,57.74 J4.5@98.04,57.74 ; 96.8,29.391 SW4.1@96.8,30.7 98.859,30.7 ; 96.8,40.309 SW4.5@96.8,39 ; 98.04,51.201 J4.4@98.04,52.66 ; 98.04,54.119 J4.4@98.04,52.66 ; 98.04,56.281 J4.5@98.04,57.74 ; 98.04,59.199 J4.5@98.04,57.74 ; 98.859,39 SW4.5@96.8,39
  other v1: 40.908,1.582 43.308,1.582 52.508,1.882 54.908,1.882 87.208,2.282 89.608,2.282 92.008,2.282 76.208,2.382 78.608,2.382 81.308,2.382 83.708,2.382 40.908,3.782 43.308,3.782 64.208,4.782 66.608,4.782 69.108,4.782 71.508,4.782 15.8,4.8 20.1,4.8 87.308,5.182 89.708,5.182 92.108,5.182 76.308,5.282 78.708,5.282 81.408,5.282 83.808,5.282 33.1,5.6 51.408,6.982 53.808,6.982 56.3,7 58.7,7 1.808,8.082 5.608,8.082 87.508,8.182 89.908,8.182 92.308,8.182 26.408,8.382 22.808,8.482 33.108,8.482 35.508,8.482 51.408,8.682 53.808,8.682 56.308,8.682 58.708,8.682 39.7,8.8 40.9,8.8 42,8.8 43.4,8.8 47.9,8.8 67.208,9.582 69.608,9.582 43.7,10.4 10.608,11.382 1.808,12.082 5.608,12.082 26.408,12.382 22.808,12.482 33.108,12.482 35.508,12.482 67.308,12.482 69.708,12.482 39.7,12.8 40.8,12.9 42,12.9 43,13.8 85.4,14.2 39.708,15.082 40.8,15.1 42.108,15.082 43,15.1 44,15.1 56.7,15.1 10.608,15.382 1.708,16.482 5.508,16.482 56.7,16.5 26.308,16.782 22.708,16.882 33.008,16.882 35.408,16.882 96.308,16.882 98.708,16.882 71.808,17.782 74.208,17.782 69.2,17.8 71.808,18.982 74.208,18.982 91.9,19.5 82.5,19.6 84.4,19.6 85.9,19.6 87.4,19.6 10.508,19.782 71.808,20.182 74.208,20.182 1.708,20.482 5.508,20.482 51.2,20.5 84.4,20.6 85.9,20.6 87.4,20.6 42.8,20.9 45,20.9 91.9,21 35.3,21.4 84.4,21.6 85.9,21.6 87.4,21.6 60.7,22 69,22.1 51.2,22.5 91.9,22.5 5.5,22.6 60.7,22.8 42.8,22.9 45,22.9 85.3,23.1 86.1,23.1 81.1,23.3 10.5,23.4 17.608,23.582 19.408,23.582 14.008,23.682 15.808,23.682 60.7,23.7 85.7,23.713 74.6,23.8 85.3,24.3 86.1,24.3 59.8,24.6 60.737,24.6 66.3,25 84.9,25.4 86.4,25.4 74.6,25.6 51.1,26.1 84.9,26.4 86.4,26.4 58,26.7 60,26.7 62.2,26.7 66.3,26.7 68.6,26.7 71.1,26.7 73.2,26.7 84.9,27.4 86.4,27.4 0.6,28 82.4,28.2 83.9,28.2 13.208,28.582 17.208,28.582 66.5,28.7 67.6,28.7 68.8,28.7 69.9,28.7 71.1,28.7 72.2,28.7 73.3,28.7 74.4,28.7 55,29.1 57,29.1 59.2,29.1 36.5,29.2 77.5,29.5 82.4,29.5 4.5,30.1 63.5,30.5 64.6,30.5 66.6,30.8 69.2,30.8 82.5,30.8 85.7,31.2 63.5,31.3 64.6,31.3 88.6,31.3 63.5,32.1 64.6,32.1 77.5,32.4 82.5,32.9 62.5,33 63.5,33 64.6,33 13.208,33.082 17.208,33.082 74.6,33.2 85.7,33.7 88.6,33.8 74.6,34.3 4.6,34.9 74.6,35.4 82.5,35.4 17.108,35.582 21.108,35.582 9.308,35.682 13.308,35.682 74.6,36.5 75.6,36.5 56.7,36.6 58.8,36.6 86.1,37.3 82.5,37.7 54.7,38.3 56.7,38.3 58.8,38.3 91.8,39.1 93.4,39.1 86.1,39.6 54.7,39.8 56.7,39.8 58.8,39.8 77,40.1 79.3,40.1 81.8,40.1 9.308,41.882 13.308,41.882 54.808,42.482 58.808,42.482 82.6,42.7 91.3,43.3 92.9,43.3 97.5,43.3 99.1,43.3 40.008,43.382 44.008,43.382 58,44.2 82.6,45 91.3,45.6 92.9,45.6 97.5,45.6 99.1,45.6 9.308,45.882 13.308,45.882 58,45.9 51.2,46.7 65.108,47.082 69.108,47.082 73.108,47.082 77.108,47.082 40.008,47.382 44.008,47.382 91.3,48.1 92.9,48.1 94.5,48.1 96.1,48.1 97.5,48.1 99.1,48.1 58,48.2 90.9,49.9 92.5,49.9 94.1,49.9 95.7,49.9 97.5,49.9 99.1,49.9 9.208,50.282 13.208,50.282 17.208,50.282 21.208,50.282 25.208,50.282 29.208,50.282 33.208,50.282 37.208,50.282 58,50.8 65.108,51.082 69.108,51.082 73.108,51.082 77.108,51.082 81.108,51.082 89.3,51.2 90.9,51.2 89.3,52.4 90.9,52.4 44.808,53.282 48.808,53.282 58,53.7 86.1,53.7 87.7,53.7 89.3,53.7 90.9,53.7 9.208,54.282 13.208,54.282 17.208,54.282 21.208,54.282 25.208,54.282 29.208,54.282 33.208,54.282 37.208,54.282 65.108,55.082 69.108,55.082 73.108,55.082 77.108,55.082 87.8,56.6 89.4,56.6 44.808,57.282 48.808,57.282 86.2,58 87.8,58 89.4,58 91,58 9.208,58.282 13.208,58.282 17.208,58.282 21.208,58.282 25.208,58.282 29.208,58.282 33.208,58.282 37.208,58.282 58,58.7 65.108,59.082 69.108,59.082 73.108,59.082 77.108,59.082 81.108,59.082 86.2,59.4 87.8,59.4 89.4,59.4 91,59.4 86.2,60.8 87.8,60.8 89.4,60.8 91,60.8 92.8,60.8 94.4,60.8 96,60.8 97.6,60.8 58,61 44.808,61.282 48.808,61.282 86.2,62.2 87.8,62.2 89.4,62.2 91,62.2 92.8,62.2 94.4,62.2 96,62.2 97.6,62.2 9.208,62.282 13.208,62.282 17.208,62.282 21.208,62.282 25.208,62.282 29.208,62.282 33.208,62.282 37.208,62.282 65.108,63.082 69.108,63.082 73.108,63.082 77.108,63.082 81.108,63.082 86.2,63.6 87.8,63.6 89.4,63.6 91,63.6 61.1,65 63.1,65 44.808,65.282 48.808,65.282 52.9,65.4 21.208,66.282 25.208,66.282 63.1,66.7 59.3,67.1 83.708,68.482 87.708,68.482 91.708,68.482 60.9,68.6 36.608,68.882 40.608,68.882 44.608,68.882 48.908,68.882 52.908,68.882 56.908,68.882
GPRS_PWRKEY: Q2.1 U1.34 | length 44.1
  TOP w0.203: U1.34@50.082,28.7 50.082,30.348 50.5,30.766 v1(50.5,30.8) ; v1(56.6,66.5) 57.4,66.5 57.6,66.3 Q2.1@57.6,66.251
  BOTTOM w0.203: v1(50.5,30.8) 50.5,64.6 52.4,66.5 v1(56.6,66.5)
GPRS_RESET: C18.2 U1.33 U6.16 | length 51.8
  TOP w0.203: U1.33@50.582,28.7 50.582,29.948 51.434,30.8 v1(51.9,30.8) ; v1(56.6,63.962) C18.2@58,63.962 64.362,63.962 65.44,65.04 U6.16@65.44,67.251
  BOTTOM w0.203: v1(51.9,30.8) 51.9,63.1 52.8,64 56.562,64 v1(56.6,63.962)
IIC_SCL: R15.1 U1.53 U4.6 | length 28.4
  TOP w0.203: U1.53@40.982,24.6 46.993,24.6 49.1,22.493 49.1,20.293 54,15.393 54,12.1 54.84,11.26 U4.6@57.185,11.26 59.698,11.26 R15.1@60.338,11.9
IIC_SDA: R13.1 U1.52 U4.5 | length 42.5
  TOP w0.203: U1.52@40.982,25.1 47.2,25.1 49.6,22.7 49.6,20.5 54.5,15.6 54.5,12.5 55.1,11.9 58.6,11.9 59.5,12.8 63.9,12.8 64.3,12.4 64.3,10.2 63.8,9.7 61.138,9.7 R13.1@60.338,10.5 59.828,9.99 U4.5@57.185,9.99
KEY0: SW2.3 U1.25 | length 85
  TOP w0.203: SW2.3@32.5,3.2 33.9,3.2 35.8,5.1 44.6,5.1 48.694,1.006 72.706,1.006 75.1,3.4 75.1,14.4 72.894,16.606 60.694,16.606 59.306,17.994 59.306,21.294 57.5,23.1 U1.25@52.682,23.1
KEY1: SW3.3 U1.50 | length 70.8
  TOP w0.203: SW3.3@8.9,3.2 9,3.3 9,20.2 7.6,21.6 1.9,21.6 1,22.5 1,26.7 1.5,27.2 9,27.2 10.1,26.1 U1.50@40.982,26.1
LED0: D1.2 U1.41 | length 95.4
  TOP w0.203: D1.2@2.074,28.2 0.6,29.674 0.6,54.4 1.376,55.176 4.899,55.176 7.2,52.875 7.2,35.5 11,31.7 45.6,31.7 46.582,30.718 U1.41@46.582,28.7
LED1: D2.2 U1.54 | length 39.9
  TOP w0.203: D2.2@2.074,26.2 2.074,26.026 3,25.1 38.2,25.1 39.2,24.1 U1.54@40.982,24.1
MQ4_AO: U1.10 U11.4 | length 41.1
  TOP w0.203: U11.4@26.72,38.4 26.72,38.38 28.8,36.3 v1(47.6,36.3) ; U1.10@47.582,17 47.6,17.018 v1(47.6,18.8)
  BOTTOM w0.203: v1(47.6,18.8) v1(47.6,36.3)
N17022771: Q3.1 R24.2 R29.1 | length 3.4
  TOP w0.203: R29.1@77.724,33.5 R24.2@77.724,35 77.724,36.562 Q3.1@77.962,36.8
N17023235: Q4.3 R29.2 | length 2.4
  TOP w0.203: R29.2@76.2,33.5 76.2,32.162 Q4.3@76.962,31.4
N17026623: D1.1 R10.2 | length 1.7
  TOP w0.203: D1.1@4.074,28.2 R10.2@5.738,28.2
N17026648: D2.1 R11.2 | length 1.7
  TOP w0.203: D2.1@4.074,26.2 R11.2@5.738,26.2
N17026724: D3.1 R16.2 | length 1.7
  TOP w0.203: D3.1@4.074,23.845 R16.2@5.738,23.845
N17028213: Q6.1 Q7.3 R41.2 | length 3.7
  TOP w0.203: Q6.1@87.6,39.8 87.6,38.238 R41.2@87.838,38 88.6,37.238 Q7.3@88.6,36.5
N17050921: C13.2 J4.1 R19.1 | length 5.8
  TOP w0.508: R19.1@89.662,55.198 C13.2@91.2,55.198 95.466,55.198 J4.1@95.484,55.216
N17050927: C14.2 R19.2 U6.60 | length 3.6
  TOP w0.508: U6.60@84.489,55.198 C14.2@86.6,55.198 R19.2@88.138,55.198
N17051220: Q2.3 U6.1 | length 25.4
  TOP w0.203: Q2.3@58,67.251 60.249,69.5 80,69.5 80.44,69.06 U6.1@80.44,67.251
N17051445: C19.1 U6.26 | length 2.5
  TOP w0.508: C19.1@58,55.184 58.016,55.2 U6.26@60.489,55.2
N17056380: C7.1 U2.3 | length 13.8
  TOP w0.4: C7.1@12.138,7.462 12.138,7.691 13.8,9.353 U2.3@13.8,20.545
N17056384: C7.2 U2.2 | length 15.8
  TOP w0.4: C7.2@12.138,5.938 11.2,6.876 11.2,8.2 13.1,10.1 U2.2@13.1,20.545
N17056392: C4.1 U2.4 | length 15.5
  TOP w0.4: C4.1@14.462,5.938 13.4,7 13.4,8.1 14.5,9.2 U2.4@14.5,20.545
N17056408: C4.2 U2.5 | length 13.4
  TOP w0.4: C4.2@14.462,7.462 15.2,8.2 U2.5@15.2,20.545
N17056584: R12.2 U2.26 | length 13.9
  TOP w0.203: R12.2@28,7.462 28,8.2 29.9,10.1 U2.26@29.9,20.545
N17056586: C11.1 U2.27 | length 13.2
  TOP w0.4: C11.1@29.7,7.716 30.6,8.616 U2.27@30.6,20.545
N17056590: C12.1 U2.28 | length 13
  TOP w0.4: U2.28@31.3,20.545 31.3,8.016 C12.1@31.6,7.716
N17058157: D5.2 U9.8 | length 22.5
  TOP w0.203: U9.8@88.15,23.713 89.187,23.713 90,22.9 90,18.675 90.268,18.406 97.006,18.406 98.5,19.9 D5.2@98.5,26.8
N17058162: D5.1 R26.1 | length 1.6
  TOP w0.254: R26.1@94.862,26.8 D5.1@96.5,26.8
N17058164: BAT1.1 C28.1 R26.2 R28.2 R31.2 SW4.3 U9.10 | length 2.4
  TOP w0.254: U9.10@88.15,24.713 90.487,24.713 90.5,24.7
N17058219: D6.2 U9.5 | length 30.1
  TOP w0.203: U9.5@83.25,22.713 83.25,19.15 83.8,18.6 89.5,18.6 90.1,18 97.175,18 99.4,20.225 99.4,27.7 98.5,28.6 D6.2@98.5,28.8
N17058224: D6.1 R28.1 | length 1.6
  TOP w0.254: R28.1@94.862,28.8 D6.1@96.5,28.8
N17058271: C27.1 F1.2 R30.2 U9.1 | length 4.2
  TOP w0.203: C27.1@88.562,12.3 R30.2@88.562,13.8
  TOP w0.254: 81,24.9 81.187,24.713 U9.1@83.25,24.713 83.25,25.05 83.2,25.1
  other v1: 88.5,9.4 89.4,9.4 90.3,9.4 91.2,9.4 92.1,9.4 88.5,10.2 89.4,10.2 90.3,10.2 91.2,10.2 92.1,10.2 80.8,25.6 81.7,25.6 82.6,25.6 83.5,25.6 80.8,26.4 81.7,26.4 82.6,26.4 83.5,26.4
N17058317: R32.1 U9.2 | length 5.9
  TOP w0.203: R32.1@80.1,21.062 80.1,23.6 80.713,24.213 U9.2@83.25,24.213
N17058321: R35.1 U9.9 | length 5.1
  TOP w0.203: U9.9@88.15,24.213 89.621,24.213 90.8,23.034 R35.1@90.8,21.062
N17058347: R33.1 U9.4 | length 3.5
  TOP w0.203: R33.1@81.5,21.062 81.5,22.6 82.113,23.213 U9.4@83.25,23.213
N17058351: R34.1 U9.7 | length 3
  TOP w0.203: U9.7@88.15,23.213 88.887,23.213 89.1,23 R34.1@89.1,21.062
N17058835: R21.2 U8.1 | length 4.4
  TOP w0.254: U8.1@67.6,24.25 67.6,24.8 68,25.2 R21.2@71.238,25.2
N17058845: R22.2 R23.1 U8.2 | length 4.1
  TOP w0.254: R23.1@65.162,25.7 R22.2@65.162,24.2 65.612,23.75 U8.2@67.6,23.75
N17058865: L1.1 U8.6 | length 3.9
  TOP w0.254: U8.6@69.1,23.25 69.65,23.25 70.1,22.8
  TOP w0.508: L1.1@70.1,20.1 70.1,22.8
N17060290: D9.1 L2.2 U10.1
N17060340: R39.1 U10.3 | length 3.1
  TOP w0.203: R39.1@65.162,29 66.112,29.95 U10.3@67.9,29.95
N17060374: R37.2 R39.2 R40.1 | length 3
  TOP w0.203: R37.2@62.062,30.4 R40.1@62.062,29 R39.2@63.638,29
N17061059: R38.2 U10.4 | length 2.5
  TOP w0.203: U10.4@70.5,29.95 R38.2@73.038,29.95
N17064279: Q1.3 R14.2 U5.2 | length 12.9
  TOP w0.203: R14.2@60.338,6.85 60.338,7.838 60.6,8.1 Q1.3@61.1,8.1 61.106,8.106 70.344,8.106 U5.2@71.6,6.85
N170520860: D4.1 R20.2 | length 1.6
  TOP w0.203: R20.2@94.862,41 94.866,41.004 D4.1@96.5,41.004
NETLED: R20.1 U6.52 | length 14.4
  TOP w0.203: U6.52@84.489,47.198 84.5,47.187 84.5,42.1 85.6,41 R20.1@93.338,41
NRST: C9.1 R8.2 U1.7 U2.14 | length 58.3
  TOP w0.203: U2.14@21.5,20.545 21.5,6.7 23.494,4.706 33.806,4.706 37,7.9 37,15.4 37.8,16.2 39.9,16.2 42.7,19 45.4,19 46.082,18.318 U1.7@46.082,17 46.082,11.412 R8.2@46.032,11.362 C9.1@44.6,11.362
OLED_CS: U1.40 U2.13 | length 41.3
  TOP w0.203: U2.13@20.8,20.545 v1(20.8,24.2) ; v1(20.8,32.6) 45.407,32.6 47.082,30.925 U1.40@47.082,28.7
  BOTTOM w0.203: v1(20.8,24.2) v1(20.8,32.6)
OLED_D0: U1.26 U2.18 | length 36.7
  TOP w0.203: U2.18@24.3,20.545 v1(24.3,24.21) ; v1(24.3,27.3) 24.4,27.3 24.5,27.2 41.786,27.2 43.186,25.8 47.386,25.8 49.586,23.6 U1.26@52.682,23.6
  BOTTOM w0.203: v1(24.3,24.21) v1(24.3,27.3)
OLED_D1: U1.27 U2.19 | length 36.9
  TOP w0.203: U2.19@25,20.545 v1(25,23.6) ; v1(25,28.1) 32.5,28.1 32.9,27.7 41.993,27.7 43.393,26.3 47.593,26.3 49.793,24.1 U1.27@52.682,24.1
  BOTTOM w0.203: v1(25,23.6) v1(25,28.1)
OLED_D2: U1.28 U2.20 | length 37.3
  TOP w0.203: U2.20@25.7,20.545 v1(25.7,24.2) ; v1(25.7,29) 32.7,29 33.5,28.2 42.2,28.2 43.6,26.8 47.8,26.8 50,24.6 U1.28@52.682,24.6
  BOTTOM w0.203: v1(25.7,24.2) v1(25.7,29)
OLED_D3: U1.55 U2.21 | length 18
  TOP w0.203: U2.21@26.4,20.545 26.4,22.626 28.468,24.694 37.706,24.694 38.8,23.6 U1.55@40.982,23.6
OLED_D4: U1.56 U2.22 | length 17.1
  TOP w0.203: U2.22@27.1,20.545 27.1,22.626 28.668,24.194 37.499,24.194 38.593,23.1 U1.56@40.982,23.1
OLED_D5: U1.57 U2.23 | length 16.1
  TOP w0.203: U2.23@27.8,20.545 27.8,22.6 28.894,23.694 37.292,23.694 38.386,22.6 U1.57@40.982,22.6
OLED_D6: U1.58 U2.24 | length 15.2
  TOP w0.203: U2.24@28.5,20.545 28.5,22.6 29.094,23.194 37.085,23.194 38.178,22.1 U1.58@40.982,22.1
OLED_D7: U1.59 U2.25 | length 14.3
  TOP w0.203: U2.25@29.2,20.545 29.2,22.49 29.403,22.694 36.878,22.694 37.971,21.6 U1.59@40.982,21.6
OLED_DC: U1.39 U2.15 | length 41.5
  TOP w0.203: U2.15@22.2,20.545 v1(22.2,23.6) ; v1(22.2,33.3) 45.414,33.3 47.582,31.132 U1.39@47.582,28.7
  BOTTOM w0.203: v1(22.2,23.6) v1(22.2,33.3)
OLED_RD: U1.37 U2.17 | length 43.6
  TOP w0.203: U2.17@23.6,20.545 v1(23.6,23.6) ; v1(23.6,34.9) 45.229,34.9 48.582,31.547 U1.37@48.582,28.7
  BOTTOM w0.203: v1(23.6,23.6) v1(23.6,34.9)
OLED_RW: U1.38 U2.16 | length 42.5
  TOP w0.203: U2.16@22.9,20.545 v1(22.9,24.21) ; v1(22.9,34.1) 45.322,34.1 48.082,31.34 U1.38@48.082,28.7
  BOTTOM w0.203: v1(22.9,24.21) v1(22.9,34.1)
OSC_IN: U1.5 X1.1 | length 9.4
  TOP w0.203: X1.1@40.3,10.6 40.3,11.35 40.95,12 42.625,12 45.082,14.457 U1.5@45.082,17
OSC_OUT: U1.6 X1.3 | length 7.6
  TOP w0.203: X1.3@42.7,10.6 42.7,11.5 45.582,14.382 U1.6@45.582,17
SPI1_MISO: U1.22 U3.2 | length 61.1
  TOP w0.203: U3.2@50.535,4.335 53.865,4.335 55.74,2.46 72.553,2.46 74.1,4.007 74.1,13.693 72.093,15.7 60.193,15.7 58.4,17.493 58.4,20.493 57.293,21.6 U1.22@52.682,21.6
SPI1_MOSI: U1.23 U3.5 | length 54.2
  TOP w0.203: U1.23@52.682,22.1 57.5,22.1 58.9,20.7 58.9,17.7 60.4,16.2 72.3,16.2 74.6,13.9 74.6,3.8 72.595,1.795 U3.5@58.435,1.795
SPI1_SCK: U1.21 U3.6 | length 50.7
  TOP w0.203: U1.21@52.682,21.1 57.086,21.1 57.9,20.286 57.9,17.286 59.986,15.2 71.886,15.2 73.6,13.486 73.6,4.214 72.451,3.065 U3.6@58.435,3.065
SWCLK: J2.2 R17.2 U1.49 | length 54.3
  TOP w0.203: J2.2@3.074,43.76 1.1,41.786 1.1,32.7 2.7,31.1 6.4,31.1 7.262,30.238 R17.2@7.262,30.2 10.862,26.6 U1.49@40.982,26.6
SWDIO: J2.3 R18.2 U1.46 | length 53.1
  TOP w0.203: J2.3@3.074,41.22 1.6,39.746 1.6,34.1 2.5,33.2 6.4,33.2 7.262,32.338 R18.2@7.262,32.3 9.362,30.2 43.6,30.2 44.082,29.718 U1.46@44.082,28.7
UIM_CLK: C20.1 CON1.3 U6.32 U7.4 | length 25.2
  TOP w0.203: CON1.3@51.355,50.65 51.355,50.945 50.7,51.6 48.6,51.6 48,51 48,49.9 46.9,48.8 U7.4@46.9,47.65 47.75,47.65 48.3,47.1 48.3,46 48.7,45.6 53.138,45.6 C20.1@54.938,47.4 55,47.4 55.8,46.6 57.334,46.6 59.934,49.2 U6.32@60.489,49.2
UIM_DATA: C21.1 CON1.7 U6.31 U7.3 | length 16.7
  TOP w0.203: CON1.7@50.355,50.65 50.355,50.455 49.1,49.2 U7.3@49.1,47.65 53.588,47.65 C21.1@54.938,49 54.938,48.862 55.6,48.2 57,48.2 59,50.2 U6.31@60.489,50.2
UIM_RST: C22.1 CON1.2 U6.33 U7.5 | length 26
  TOP w0.203: CON1.2@47.165,50.65 47.165,49.965 46,48.8 46,47.3 46.3,47 U7.5@46.9,47 47.494,47 47.794,46.7 47.794,45.832 48.432,45.194 54.332,45.194 C22.1@54.938,45.8 54.938,45.762 55.7,45 61.5,45 62,45.5 62,47.8 61.6,48.2 U6.33@60.489,48.2
UIM_VDD: C23.2 CON1.1 U6.30 U7.6 | length 32.2
  TOP w0.203: CON1.1@45.165,50.65 45.165,46.735 45.55,46.35 U7.6@46.9,46.35 46.9,45.7 47.813,44.787 54.351,44.787 C23.2@54.938,44.2 55,44.2 55.8,43.4 62,43.4 62.5,43.9 62.5,50.7 62,51.2 U6.30@60.489,51.2
USART1_RX: J3.4 U1.43 | length 62
  TOP w0.203: J3.4@3.074,51.38 5.32,51.38 6,50.7 6,35.2 10.5,30.7 45.3,30.7 45.582,30.418 U1.43@45.582,28.7
USART1_TX: J3.3 U1.42 | length 64.9
  TOP w0.203: J3.3@3.074,53.92 5.58,53.92 6.5,53 6.5,35.275 10.575,31.2 45.4,31.2 46.082,30.518 U1.42@46.082,28.7
USART2_RX: U1.17 U6.9 | length 71.9
  TOP w0.203: U1.17@52.682,19.1 53.1,19.1 53.5,18.7 v1(53.5,17.9) ; v1(56.6,65.7) 56.9,65.4 59.1,65.4 62.794,69.094 72.006,69.094 72.44,68.66 U6.9@72.44,67.251
  BOTTOM w0.203: v1(53.5,17.9) 53.5,60.5 55.6,62.6 57.2,62.6 57.8,63.2 57.8,64.534 56.634,65.7 v1(56.6,65.7)
USART2_TX: U1.16 U6.10 | length 73.9
  TOP w0.203: U1.16@50.582,17 50.582,16.618 51.5,15.7 v1(52.6,15.7) ; v1(56.6,64.8) 59.075,64.8 62.962,68.687 71.1,68.687 71.44,68.347 U6.10@71.44,67.251
  BOTTOM w0.203: v1(52.6,15.7) 52.6,62.2 53.5,63.1 56.9,63.1 57.3,63.5 57.3,64.196 56.696,64.8 v1(56.6,64.8)
VCC_3.3V: C1.1 C2.2 C3.2 C5.2 C6.2 C10.2 C25.1 C26.1 J2.4 J3.2 L1.2 R1.1 R2.2 R3.2 R5.2 R8.1 R10.1 R11.1 R13.2 R14.1 R15.2 R16.1 R18.1 R22.1 SW1.2 TP1.1 U1.1 U1.19 U1.32 U1.48 U1.64 U2.6 U2.9 U3.3 U3.7 U3.8 U4.8 U5.1 U8.4 | length 222.2
  TOP w0.254: C2.2@39.162,19.1 U1.64@40.982,19.1 ; C6.2@39.162,29 v1(40.3,29) 42.828,29 43.082,28.746 U1.48@43.082,28.7 ; v1(42.1,17) U1.1@43.082,17 ; U1.19@52.682,20.1 53.838,20.1 C5.2@55.038,18.9 ; U1.32@52.682,26.6 C3.2@55.338,26.6 ; R22.1@63.638,24.2 63.712,24.2 C26.1@65.162,22.75 ; 66.6,22.8 66.65,22.75 U8.4@67.6,22.75 67.6,22.2
  TOP w0.508: v1(3.1,32.3) R18.1@5.738,32.3 ; R16.1@7.262,23.845 v1(8.355,23.845) ; R11.1@7.262,26.2 v1(8.3,26.2) ; R10.1@7.262,28.2 v1(8.3,28.2) ; U2.6@15.9,20.545 15.9,18.3 v1(16.9,17.3) 18,18.4 U2.9@18,20.545 ; v1(16.9,4.8) 16.9,5.538 R3.2@17.3,5.938 R2.2@18.7,5.938 ; SW1.2@25.1,3.2 v1(26.7,3.2) ; v1(39.162,17.038) C2.2@39.162,19.1 ; v1(45.5,5.6) 46.665,5.6 R1.1@46.67,5.605 46.67,4.03 47.6,3.1 50.5,3.1 U3.3@50.535,3.065 ; R8.1@46.032,9.838 45.5,9.306 v1(45.5,7.2) 48.3,7.2 48.962,7.862 R5.2@48.962,9.838 ; v1(55.038,17.862) C5.2@55.038,18.9 ; C3.2@55.338,26.6 56.279,25.659 61.292,25.659 61.8,25.151 61.8,22.9 64.415,20.285 C25.1@64.415,20.1 ; U4.8@57.185,13.8 v1(59.2,13.8) C10.2@60.338,13.8 ; U3.7@58.435,4.335 59.673,4.335 C1.1@60.338,5 ; U3.8@58.435,5.605 59.733,5.605 C1.1@60.338,5 ; R13.2@61.862,10.5 R15.2@61.862,11.9 v1(63.2,11.9) ; U5.1@66.6,6.85 v1(63.2,6.85) R14.1@61.862,6.85 61.862,6.524 C1.1@60.338,5
  BOTTOM w0.508: J3.2@3.074,56.46 2.96,56.46 1.3,54.8 1.3,40.454 J2.4@3.074,38.68 3.1,38.654 v1(3.1,32.3) 3.1,29.5 4.4,28.2 v1(8.3,28.2) v1(8.3,26.2) 8.3,23.9 v1(8.355,23.845) 8.355,19.245 10.3,17.3 v1(16.9,17.3) v1(16.9,4.8) 18.5,3.2 v1(26.7,3.2) 36.076,3.2 38.476,5.6 ; 38.476,17 38.476,5.6 ; v1(40.3,29) 39.162,27.862 v1(39.162,17.038) 42.062,17.038 v1(42.1,17) ; v1(45.5,7.2) v1(45.5,5.6) 38.476,5.6 ; v1(59.2,13.8) 59.2,18.3 ; v1(63.2,6.85) v1(63.2,11.9) 63.2,18
  other v1: 65.8,17.5 66.6,17.5 67.4,17.5 65.8,18.2 66.6,18.2 67.4,18.2
VCC_5V_SENSOR: C30.1 C31.1 D9.2 R37.1 TP3.1 U11.1 | length 4.1
  TOP w0.203: R37.1@60.538,30.4 C31.1@60.538,31.85
  TOP w2: U11.1@19.1,38.4 19.1,41.1
VCC_BAT: D7.1 Q5.3 Q6.2 R41.1 SW4.4 TP2.1
  other v1: 82.4,12.1 83.2,12.1 84,12.1 82.4,12.9 83.2,12.9 84,12.9 93,36.4 94.1,36.4 95.2,36.4 93,37.3 94.1,37.3 95.2,37.3
VCC_DCDC: C24.1 D7.2 D8.2 Q3.2 Q5.2 R21.1 R24.1 U8.7 | length 8.4
  TOP w0.203: C24.1@71.238,23.75 72.688,25.2 R21.1@72.762,25.2 ; R24.1@76.2,35 76.7,35.5 76.7,38.2 77.2,38.7
  TOP w0.254: U8.7@69.1,23.75 70.2,23.75
  TOP w0.508: 70.2,23.75 C24.1@71.238,23.75
VCC_GPRS: C15.2 C16.2 C17.1 Q6.3 U6.55 U6.56 U6.57
VCC_SENSOR: C29.1 L2.1 Q3.3 R38.1 U10.5 | length 2.5
  TOP w0.508: C29.1@73.038,31.85 73.038,31.762 74.562,30.238 R38.1@74.562,29.95
VCC_USB: D8.1 F1.1 Q5.1 R36.1 USB1.1 | length 1.1
  TOP w0.254: 94.5,10 94.51,9.99 USB1.1@95.57,9.99
VDDA: C8.2 R5.1 U1.13 | length 5.7
  TOP w0.254: R5.1@48.962,11.362 C8.2@48.962,12.956 49.082,13.076 U1.13@49.082,17
VSSA: C8.1 R9.1 U1.12 | length 6.1
  TOP w0.254: R9.1@47.438,11.362 C8.1@47.438,12.956 48.582,14.1 U1.12@48.582,17
WK_UP: SW1.3 U1.14 | length 40.7
  TOP w0.203: SW1.3@20.7,3.2 21.8,4.3 34.1,4.3 36.3,6.5 48.9,6.5 50,7.6 50,13.6 49.582,14.018 U1.14@49.582,17
pads on no net: CON1.4 CON1.6 SW4.2 U1.2 U1.3 U1.4 U1.11 U1.15 U1.24 U1.30 U1.44 U1.45 U1.51 U1.61 U1.62 U2.10 U6.2 U6.3 U6.4 U6.5 U6.6 U6.7 U6.8 U6.11 U6.12 U6.13 U6.14 U6.15 U6.19 U6.20 U6.21 U6.22 U6.23 U6.24 U6.25 U6.27 U6.28 U6.34 U6.35 U6.36 U6.37 U6.38 U6.40 U6.41 U6.42 U6.43 U6.44 U6.47 U6.48 U6.49 U6.50 U6.51 U6.53 U6.66 U6.67 U6.68 U7.1 U8.8 U9.6 U11.3 USB1.2 USB1.3 USB1.4

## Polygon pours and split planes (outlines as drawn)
GND on TOP "TOP-GND" (solid, pour order 363): -0.05,2.9 ccw(c2.9,2.9) 2.9,-0.05 97.1,-0.05 ccw(c97.1,2.9) 100.05,2.899 100.05,2.9 100.05,67.1 100.05,67.101 ccw(c97.1,67.1) 97.1,70.05 2.9,70.05 ccw(c2.9,67.1) -0.05,67.1
GND on TOP "TOP-GND 1" (solid, pour order 326): 373 vertices, not listed, extent 20.201,0.2 25.599,3.741
GND on TOP "TOP-GND 2" (solid, pour order 312): 138 vertices, not listed, extent 94.257,29.657 95.743,33.643
GND on TOP "TOP-GND 3" (solid, pour order 80): 41.73,19.619 41.582,19.75 40.95,19.6 41.582,19.45 41.73,19.581 41.732,19.592 41.732,19.603 41.731,19.614 41.73,19.619
GND on TOP "TOP-GND 4" (solid, pour order 79): 40.234,19.581 40.382,19.45 41.014,19.6 40.382,19.75 40.234,19.619 40.232,19.608 40.232,19.597 40.233,19.586 40.234,19.581
GND on TOP "TOP-GND 5" (solid, pour order 76): 83.998,23.732 83.85,23.863 83.218,23.713 83.85,23.563 83.998,23.694 84,23.705 84,23.716 83.999,23.727 83.998,23.732
GND on TOP "TOP-GND 6" (solid, pour order 72): 82.502,23.694 82.65,23.563 83.282,23.713 82.65,23.863 82.502,23.732 82.5,23.721 82.5,23.71 82.501,23.699 82.502,23.694
GND on TOP "TOP-GND 7" (solid, pour order 145): 96.462,12.634 96.27,12.79 95.538,12.59 96.27,12.39 96.462,12.547 96.466,12.557 96.468,12.568 96.469,12.579 96.47,12.59 96.469,12.601 96.468,12.612 96.466,12.623 96.462,12.633 96.462,12.634
GND on TOP "TOP-GND 8" (solid, pour order 81): 51.934,19.581 52.082,19.45 52.714,19.6 52.082,19.75 51.934,19.619 51.932,19.608 51.932,19.597 51.933,19.586 51.934,19.581
GND on TOP "TOP-GND 9" (solid, pour order 62): 25 vertices, not listed, extent 54.195,25.777 54.522,26.105
GND on TOP "TOP-GND 10" (solid, pour order 94): 43.551,29.445 43.432,29.3 43.582,28.675 43.732,29.3 43.613,29.445 43.605,29.447 43.596,29.449 43.587,29.45 43.578,29.45 43.569,29.449 43.561,29.448 43.552,29.445 43.551,29.445
GND on TOP "TOP-GND 11" (solid, pour order 114): 43.613,27.955 43.732,28.1 43.582,28.725 43.432,28.1 43.551,27.955 43.559,27.953 43.568,27.951 43.577,27.95 43.586,27.95 43.595,27.951 43.603,27.952 43.612,27.955 43.613,27.955
GND on TOP "TOP-GND 12" (solid, pour order 82): 51.934,26.081 52.082,25.95 52.714,26.1 52.082,26.25 51.934,26.119 51.932,26.108 51.932,26.097 51.933,26.086 51.934,26.081
GND on TOP "TOP-GND 13" (solid, pour order 83): 53.43,26.119 53.282,26.25 52.65,26.1 53.282,25.95 53.43,26.081 53.432,26.092 53.432,26.103 53.431,26.114 53.43,26.119
GND on TOP "TOP-GND 14" (solid, pour order 223): 19 vertices, not listed, extent 74.138,42.151 74.738,43.283
GND on TOP "TOP-GND 15" (solid, pour order 224): 19 vertices, not listed, extent 75.138,42.151 75.738,43.283
GND on TOP "TOP-GND 16" (solid, pour order 225): 19 vertices, not listed, extent 68.138,42.151 68.738,43.283
GND on TOP "TOP-GND 17" (solid, pour order 70): 49.592,47.044 49.4,47.2 49.068,47 49.4,46.8 49.592,46.956 49.596,46.967 49.598,46.978 49.599,46.989 49.6,47 49.599,47.011 49.598,47.022 49.596,47.033 49.592,47.043 49.592,47.044
GND on TOP "TOP-GND 18" (solid, pour order 324): 96 vertices, not listed, extent 48.389,1.565 57.178,3.776
GND on TOP "TOP-GND 19" (solid, pour order 335): 165 vertices, not listed, extent 61.181,4.259 72.541,7.547
GND on TOP "TOP-GND 20" (solid, pour order 313): 100 vertices, not listed, extent 46.211,7.911 48.251,10.509
GND on TOP "TOP-GND 21" (solid, pour order 285): 73 vertices, not listed, extent 44.497,12.1 45.523,13.245
GND on TOP "TOP-GND 22" (solid, pour order 347): 88 vertices, not listed, extent 61.195,8.079 72.541,14.141
GND on TOP "TOP-GND 23" (solid, pour order 351): 277 vertices, not listed, extent 49.84,4.259 60.843,15.953
GND on TOP "TOP-GND 24" (solid, pour order 349): 319 vertices, not listed, extent 37.237,7.059 45.202,16.701
GND on TOP "TOP-GND 25" (solid, pour order 361): 232 vertices, not listed, extent 22.059,5.265 38.451,22.135
GND on TOP "TOP-GND 26" (solid, pour order 355): 308 vertices, not listed, extent 73.937,1.159 86.304,22.395
GND on TOP "TOP-GND 27" (solid, pour order 336): 177 vertices, not listed, extent 68.4,15.535 75.043,22.669
GND on TOP "TOP-GND 28" (solid, pour order 315): 109 vertices, not listed, extent 50.159,19.43 51.748,23.041
GND on TOP "TOP-GND 29" (solid, pour order 277): 59 vertices, not listed, extent 80.659,21.864 81.476,23.654
GND on TOP "TOP-GND 30" (solid, pour order 339): 274 vertices, not listed, extent 41.916,18.046 50.448,24.041
GND on TOP "TOP-GND 31" (solid, pour order 317): 99 vertices, not listed, extent 90.559,18.965 92.6,24.143
GND on TOP "TOP-GND 32" (solid, pour order 329): 80 vertices, not listed, extent 59.23,17.859 62.843,24.947
GND on TOP "TOP-GND 33" (solid, pour order 319): 139 vertices, not listed, extent 43.625,25.159 51.748,27.68
GND on TOP "TOP-GND 34" (solid, pour order 314): 57 vertices, not listed, extent 33.137,28.759 38.306,29.641
GND on TOP "TOP-GND 35" (solid, pour order 342): 143 vertices, not listed, extent 8.119,27.159 25.043,30.508
GND on TOP "TOP-GND 36" (solid, pour order 341): 373 vertices, not listed, extent 56.195,21.857 78.543,32.812
GND on TOP "TOP-GND 37" (solid, pour order 344): 222 vertices, not listed, extent 84.759,27.857 91.108,36.502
